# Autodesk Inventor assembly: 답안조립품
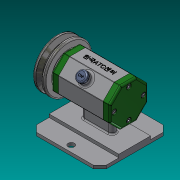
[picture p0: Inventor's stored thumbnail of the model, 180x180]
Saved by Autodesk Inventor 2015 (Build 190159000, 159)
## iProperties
Created: 2018-06
Part Number: 답안조립품
Document SubType Name: Assembly
Designer: Administrator
Author: Administrator
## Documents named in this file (16)
- C:\Users\Administrator\Desktop\480608V1016\답안조립품.iam
- C:\Users\Administrator\Desktop\480608V1016\본체.ipt
- C:\Users\Administrator\Desktop\480608V1016\V벨트풀리.ipt
- C:\Users\Administrator\Desktop\480608V1016\고무캡.ipt
- C:\Users\Administrator\Desktop\480608V1016\너트 M8.ipt
- 너트 M8.ipt
- C:\Users\Administrator\Desktop\480608V1016\뒤커버.ipt
- C:\Users\Administrator\Desktop\480608V1016\베어링 15x32x9.ipt
- C:\Users\Administrator\Desktop\480608V1016\스프링와셔 8.ipt
- C:\Users\Administrator\Desktop\480608V1016\앞커버.ipt
- C:\Users\Administrator\Desktop\480608V1016\오일 실 15 25 7.ipt
- C:\Users\Administrator\Desktop\480608V1016\와셔 8x17.ipt
- C:\Users\Administrator\Desktop\480608V1016\축.ipt
- C:\Users\Administrator\Desktop\480608V1016\키 3x3x12.ipt
- 키 3x3x12.ipt
- C:\Users\Administrator\Desktop\480608V1016\볼트 M4x12.ipt
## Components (2 placed, 2 different names)
1. V벨트풀리:1 — 각도:3
2. 고무캡:1 — 각도:7
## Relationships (2: Angle 2)
- 각도:3 [Angle]: V벨트풀리:1
- 각도:7 [Angle]: 고무캡:1
